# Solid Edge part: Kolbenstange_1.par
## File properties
Username: bmolnar
Dokumentum tartalom típus: 0
Author: bmolnar
Last saved by: bmolnar
Revision: 96
Sűrűség: 0,000 kg/m^3
Pontosság: 0,990
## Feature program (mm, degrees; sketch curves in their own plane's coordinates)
base feature "unnamed BaseFeature 1"
thread "unnamed Thread 1"
chamfer "Letörés_1"  SetBackValue2 = 20 deg
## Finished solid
Body 1: solid body, 19 faces, 27 edges, 11 vertices.
  Faces by surface: plane 8, cylinder 5, cone 3, torus 3
  Edges by curve: circle 15, line 7, curve on surface 3, ellipse 2
Bounding box of the edges (mm; curved faces can reach further): 100.000 x 100.000 x 2688.500, from (-50, -50, -86.75) to (50, 50, 2601.75).
Cylindrical faces by radius (mm): R8.75 x1, R10 x1, R12.25 x1, R12.5 x1, R50 x1
Conical faces (half-angle, radius in mm at the cone's reference point): 20 deg R10 x1, 30 deg R12.375 x1, 60 deg R9.375 x1
Toroidal faces (ring radius, tube radius in mm): R9.15 r0.4 x2, R10.45 r1.8 x1
Planar faces by outward normal: +x 1, +z 3, -x 1, -z 1, oblique 2
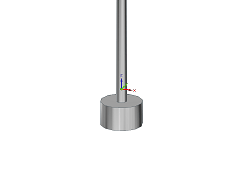
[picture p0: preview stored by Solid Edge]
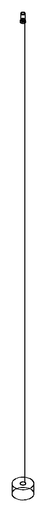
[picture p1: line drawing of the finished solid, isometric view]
